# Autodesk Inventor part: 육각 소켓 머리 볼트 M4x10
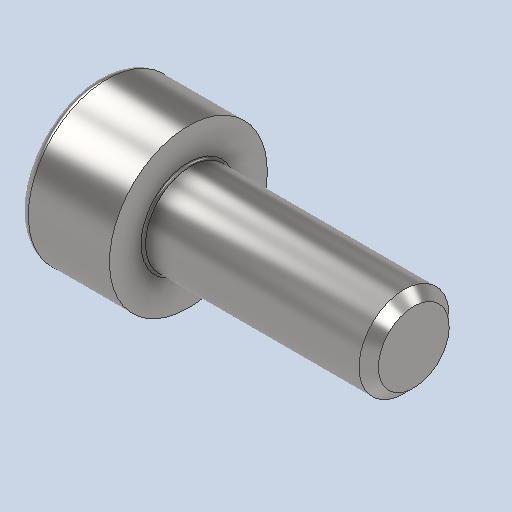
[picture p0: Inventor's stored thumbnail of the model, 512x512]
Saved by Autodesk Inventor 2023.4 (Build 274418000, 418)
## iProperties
Created: 2024-09
Part Number: 육각 소켓 머리 볼트 M4x10
Material: 강철, 연강
Description: 6각머리 태핑 나사
Document SubType Name: Modeling
Designer: EDU
Density: 7.85 g/cm^3
Appearance: 기본값
Author: jhkim
Sending System: Autodesk Inventor 2025
Preprocessor: ST-DEVELOPER v20
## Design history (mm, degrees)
feature "Solid1"
node "솔리드1"
